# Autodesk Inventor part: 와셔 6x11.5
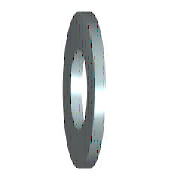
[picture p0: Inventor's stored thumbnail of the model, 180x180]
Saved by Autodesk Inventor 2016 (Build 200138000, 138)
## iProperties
Created: 2012-02
Part Number: 와셔 6x11.5
Material: 강철, 연강
Description: 평면 와셔
Document SubType Name: Modeling
Standard: KS B 1326
Designer: mduedu
Standards Organization: KS
Language: ko-KR
Size Designation: 6x11.5
Categories: <MemberInstance><Categories><Category DisplayName="조임쇠" InternalName="e4da775c-781d-43d5-af7c-5136215cf5a6" Mnemonic="FSTN"><Category DisplayName="와셔" InternalN
Density: 1 g/cm^3
Appearance: 주황색
IsCustomPart: 1
Author: mduedu
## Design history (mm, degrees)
sketch "스케치"
  geometry: C1 r 5.75 at (0, 0); C2 r 3.2 at (0, 0); 1 further point
  constraints: 2 centre point, 2 coincident
  dimensions: "d0" = 6.4 diameter of C2 (= SD1); "d1" = 11.5 diameter of C1 (= SD2)
extrude "본체" new body sketch "스케치" distance "d2" = 1.6 (= SD); taper "d3" = 0 deg
workaxis "Work Axis1"
workplane "Work Plane1"
body "Solid1"
other parameters: "SD1" = 6.4 [user parameter; used in 1 equation term], "SD2" = 11.5 [user parameter; used in 1 equation term], "SD" = 1.6 [user parameter; used in 1 equation term], "d4" = 0, "d5" = 0, "d6" = 0, "d7" = 0, "NND" = 6 [user parameter]
